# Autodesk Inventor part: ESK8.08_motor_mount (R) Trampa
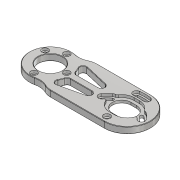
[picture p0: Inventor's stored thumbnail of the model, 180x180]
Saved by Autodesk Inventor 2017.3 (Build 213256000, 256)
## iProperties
Created: 2018-01
Part Number: ESK8.08_motor_mount (R) Trampa
Material: Aluminium 7075-T6
Document SubType Name: Modeling
Designer: Tobias
Density: 2.81 g/cm^3
Appearance: Machined - Aluminum
Mass: 107.535 g
Surface Area: 179.533 cm^2
Volume: 38.2686 cm^3
Author: Tobias
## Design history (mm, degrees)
sketch "Sketch1"
  geometry: L1 (0, 66.175)-(0, -66.175) reference; L2 (-56.3, 0)-(155.8, 0) reference; L3 (24, -29)-(96.5, -29); L4 (24, 29)-(96.5, 29); A1 r 26 centre (0, 0) between (5.824, 25.339) and (5.824, -25.339); A2 r 29 centre (96.5, 0) between (96.5, -29) and (96.5, 29); A3 r 22.5 centre (10.864, 47.268) between (5.824, 25.339) and (24, 29); A4 r 22.5 centre (10.864, -47.268) between (24, -29) and (5.824, -25.339); 1 further point
  constraints: 8 point on circle, 4 centre point, 4 end point, 2 horizontal, 2 tangent, 1 coincident, 1 point on line, 1 symmetric about line
  dimensions: "d144" = 52 diameter of A1; "d199" = 24 distance from line of L4.start L1; "d274" = 96.5 distance from line of L1 A2.centre; "d275" = 29 radius of A2; "d357" = 58 distance between parallel lines of L3 L4; "d492" = 45 diameter of A3; "d498" = 22.5 radius of A4 (derived)
extrude "Extrusion1" new body sketch "Sketch1" stored distance "d6" = 8; taper "d7" = 0 deg
sketch "Sketch3"
  geometry: L1 (0, 40.6)-(0, -40.6) reference; L2 (-56.3, 0)-(155.8, 0) reference; C1 r 15 at (0, 0); 1 further point
  constraints: 1 centre point, 1 coincident
  dimensions: "d12" = 30 diameter of C1
extrude "Extrusion3" cut sketch "Sketch3" distance "d13" = 89.75; taper "d14" = 0 deg
sketch "Sketch24"
  geometry: L1 (0, -40.6)-(0, 40.6) reference; L2 (-155.8, 0)-(56.3, 0) reference; L3 (-89.5, 0)-(-96.5, 0); L4 (-89.5, 27)-(-96.5, 27); L5 (-96.5, -27)-(-89.5, -27); A1 r 27 centre (-89.5, 0) between (-89.5, -27) and (-89.5, 27); A2 r 27 centre (-96.5, 0) between (-96.5, 27) and (-96.5, -27); 2 further points
  constraints: 8 end point, 4 point on circle, 4 tangent, 2 centre point, 2 point on line, 1 midpoint, 1 parallel
  dimensions: "d220" = 54 distance between parallel lines of L4 L5; "d221" = 93 distance from line of L1 point (-93, 0); "d222" = 7 distance of L3.start L3.end
extrude "Extrusion19" cut sketch "Sketch24" distance "d223" = 1.5; taper "d224" = 0 deg
sketch "Sketch29"
  geometry: L1 (0, 48)-(0, -85) reference; L2 (-58.6, 0)-(169.6, 0) reference; L3 (93, -22)-(93, 0); L4 (86.496, 21.517)-(93, -22); L5 (99.504, 21.517)-(93, -22); L6 (93, -22)-(74.501, 3); L7 (93, -22)-(68, -3.501); L8 (93, -22)-(111.499, 3); L9 (118, -3.501)-(93, -22); C1 r 1.5 at (93, -22); A1 r 2.05 centre (86.496, 21.517) between (86.193, 23.544) and (86.799, 19.489); A2 r 2.05 centre (99.504, 21.517) between (99.201, 19.489) and (99.807, 23.544); A3 r 31.1 centre (93, -22) between (68, -3.501) and (74.501, 3); A4 r 2.05 centre (68, -3.501) between (66.352, -2.282) and (69.648, -4.72); A5 r 2.05 centre (74.501, 3) between (75.72, 1.352) and (73.282, 4.648); A6 r 33.15 centre (93, -22) between (73.282, 4.648) and (66.352, -2.282); A7 r 29.05 centre (93, -22) between (75.72, 1.352) and (69.648, -4.72); A8 r 2.05 centre (111.499, 3) between (112.718, 4.648) and (110.28, 1.352); A9 r 2.05 centre (118, -3.501) between (116.352, -4.72) and (119.648, -2.282); A10 r 33.15 centre (93, -22) between (119.648, -2.282) and (112.718, 4.648); A11 r 29.05 centre (93, -22) between (116.352, -4.72) and (110.28, 1.352); A12 r 44 centre (93, -22) between (86.496, 21.517) and (99.504, 21.517); A13 r 41.95 centre (93, -22) between (99.201, 19.489) and (86.799, 19.489); A14 r 46.05 centre (93, -22) between (99.807, 23.544) and (86.193, 23.544); 1 further point
  constraints: 30 point on circle, 15 centre point, 14 end point, 9 tangent, 8 coincident, 1 perpendicular, 1 point on line, 2 other
  dimensions: "d276" = 93 distance between parallel lines of L3 L1; "d277" = 2.05 radius of A1; "d283" = 22 distance from line of L3.start L2; "d284" = 88 diameter of A12; "d293" = 17 deg angle of L7 L6 (derived); "d295" = 62.2 diameter of A3; "d296" = 17 deg angle of L5 L4; "d297" = 2.05 radius of A5 (derived); "d298" = 2.05 radius of A8 (derived); "d301" = 17 deg angle of L9 L8; "d315" = 3 diameter of C1; "d470" = 107 deg angle of L9 L7
extrude "Extrusion23" cut sketch "Sketch29" distance "d272" = 49.25; taper "d273" = 0 deg
sketch "Sketch30"
  geometry: L1 (89.5, 0)-(96.5, 0); L2 (89.5, 11.7)-(96.5, 11.7); L3 (96.5, -11.7)-(89.5, -11.7); L4 (0, 40.6)-(0, -40.6) reference; L5 (-56.3, 0)-(155.8, 0) reference; A1 r 11.7 centre (89.5, 0) between (89.5, 11.7) and (89.5, -11.7); A2 r 11.7 centre (96.5, 0) between (96.5, -11.7) and (96.5, 11.7); 2 further points
  constraints: 8 end point, 4 point on circle, 4 tangent, 2 centre point, 1 horizontal, 1 midpoint, 1 parallel, 1 point on line
  dimensions: "d306" = 93 distance from line of L4 point (93, 0) (derived); "d307" = 7 distance of L1.start L1.end; "d308" = 23.4 distance between parallel lines of L2 L3
extrude "Extrusion24" cut sketch "Sketch30" distance "d281" = 28.75; taper "d282" = 0 deg
sketch "Sketch36"
  geometry: L1 (0, 40.6)-(0, -40.6) reference; L2 (-56.3, 0)-(155.8, 0) reference; L3 (26.889, 18.895)-(56.908, 11.895); L4 (28.914, 4)-(56, 4); A1 r 26 centre (0, 0) between (25.059, 6.933) and (22.517, 13); A2 r 4 centre (25.981, 15) between (26.889, 18.895) and (22.517, 13); A3 r 4 centre (28.914, 8) between (25.059, 6.933) and (28.914, 4); A4 r 4 centre (56, 8) between (56, 4) and (56.908, 11.895); 1 further point
  constraints: 8 point on circle, 6 tangent, 4 centre point, 4 end point, 1 coincident, 1 parallel
  dimensions: "d369" = 26 radius of A1; "d370" = 8 distance from line of L2 A4.centre; "d371" = 4 radius of A3; "d372" = 4 radius of A2; "d373" = 4 radius of A4; "d374" = 15 distance from line of L2 A2.centre (derived); "d376" = 56 distance from line of A4.centre L1; "d409" = 13.1259 deg angle of L4 L3 (derived)
extrude "Extrusion30" cut sketch "Sketch36" stored distance "d365" = 4; taper "d366" = 0 deg
mirror "Mirror8"
sketch "Sketch37"
  geometry: C1 r 1.5 at (93, -22) reference; A1 r 33.15 centre (93, -22) between (73.282, 4.648) and (66.352, -2.282) reference; A2 r 2.05 centre (74.501, 3) between (75.72, 1.352) and (73.282, 4.648) reference; A3 r 29.05 centre (93, -22) between (75.72, 1.352) and (69.648, -4.72) reference; A4 r 2.05 centre (68, -3.501) between (66.352, -2.282) and (69.648, -4.72) reference; A5 r 2.05 centre (86.496, 21.517) between (86.193, 23.544) and (86.799, 19.489) reference; A6 r 41.95 centre (93, -22) between (99.201, 19.489) and (86.799, 19.489) reference; A7 r 2.05 centre (99.504, 21.517) between (99.201, 19.489) and (99.807, 23.544) reference; A8 r 46.05 centre (93, -22) between (99.807, 23.544) and (86.193, 23.544) reference; A9 r 2.05 centre (111.499, 3) between (112.718, 4.648) and (110.28, 1.352) reference; A10 r 33.15 centre (93, -22) between (119.648, -2.282) and (112.718, 4.648) reference; A11 r 29.05 centre (93, -22) between (116.352, -4.72) and (110.28, 1.352) reference; A12 r 2.05 centre (118, -3.501) between (116.352, -4.72) and (119.648, -2.282) reference; A13 r 35.3 centre (93, -22) between (121.376, -1.003) and (113.997, 6.376); A14 r 4.2 centre (111.499, 3) between (113.997, 6.376) and (109.001, -0.376); A15 r 26.9 centre (93, -22) between (114.624, -5.999) and (109.001, -0.376); A16 r 4.2 centre (118, -3.501) between (114.624, -5.999) and (121.376, -1.003); A17 r 4.2 centre (86.496, 21.517) between (85.876, 25.671) and (87.117, 17.363); A18 r 48.2 centre (93, -22) between (100.124, 25.671) and (85.876, 25.671); A19 r 4.2 centre (99.504, 21.517) between (98.883, 17.363) and (100.124, 25.671); A20 r 39.8 centre (93, -22) between (98.883, 17.363) and (87.117, 17.363); A21 r 35.3 centre (93, -22) between (72.003, 6.376) and (64.624, -1.003); A22 r 4.2 centre (74.501, 3) between (76.999, -0.376) and (72.003, 6.376); A23 r 26.9 centre (93, -22) between (76.999, -0.376) and (71.376, -5.999); A24 r 4.2 centre (68, -3.501) between (64.624, -1.003) and (71.376, -5.999); 1 further point
  constraints: 24 point on circle, 12 centre point, 9 other
  dimensions: "d377" = 4.2 radius of A17 (derived); "d378" = 4.2 radius of A22; "d379" = 4.2 radius of A14 (derived)
extrude "Extrusion31" cut sketch "Sketch37" distance "d381" = 3.3; taper "d382" = 0 deg
sketch "Sketch48"
  geometry: L1 (0, 40.6)-(0, -40.6) reference; L2 (-56.3, 0)-(155.8, 0) reference; L3 (0, 20.5)-(0, 0); L4 (0, 0)-(20.5, 0); L5 (0, 0)-(0, -20.5); L6 (-17.385, 10.863)-(0, 0); L7 (0, 0)-(17.93, 9.939); C1 r 15 at (0, 0) reference; A1 r 20.5 centre (0, 0) between (0, 20.5) and (0, -20.5); 1 further point
  constraints: 10 end point, 5 point on circle, 1 centre point, 1 coincident, 1 other
  dimensions: "d414" = 41 diameter of A1; "d462" = 29 deg angle of L7 L2; "d463" = 58 deg angle of L3 L6; "d464" = 90 deg angle of L4 L5; "d465" = 90 deg angle of L3 L4
hole "Hole6" sketch "Sketch48" at (0, 20.5), (20.5, 0), (0, -20.5), (-17.385, 10.863) diameter "d415" = 4.2; stored, may be unused: countersink angle "d419" = 90 deg, drill point angle "d421" = 118 deg; dims "d416" = 6, "d417" = 8, "d418" = 3, "d420" = 8
sketch "Sketch59"
  geometry: L1 (0, 40.6)-(0, -40.6) reference; L2 (-56.3, 0)-(155.8, 0) reference; L3 (89.5, 0)-(96.5, 0); L4 (89.5, -15.5)-(96.5, -15.5); L5 (96.5, 15.5)-(89.5, 15.5); A1 r 15.5 centre (89.5, 0) between (89.5, 15.5) and (89.5, -15.5); A2 r 15.5 centre (96.5, 0) between (96.5, -15.5) and (96.5, 15.5); 2 further points
  constraints: 8 end point, 4 point on circle, 4 tangent, 2 centre point, 2 point on line, 1 midpoint, 1 parallel
  dimensions: "d483" = 93 distance from line of L1 point (93, 0) (derived); "d484" = 7 distance of L3.end L3.start; "d486" = 31 distance between parallel lines of L4 L5
extrude "Extrusion49" cut sketch "Sketch59" distance "d487" = 3.3; taper "d488" = 0 deg
fillet "Fillet54" dims "d489" = 1.5
fillet "Fillet56" dims "d491" = 3
fillet "Fillet57" dims "d496" = 20
sketch "Sketch68"
  geometry: C1 r 1.5 at (93, -22) reference; 2 further points
  constraints: 1 coincident
hole "Hole10" sketch "Sketch68" at (93, -22) diameter "d545" = 4; stored, may be unused: countersink angle "d549" = 90 deg, drill point angle "d551" = 118 deg; dims "d546" = 6, "d547" = 8.4, "d548" = 3.3, "d550" = 8
chamfer "Chamfer13" distance "d456" = 0.5; stored, may be unused: second distance "d457" = 2, angle "d458" = 45 deg
body "Solid1"
other parameters: "d3" = 82, "d68" = 52, "sa_0" = 0, "sa_1" = 0, "sa_2" = 1000000, "d380" = 8
